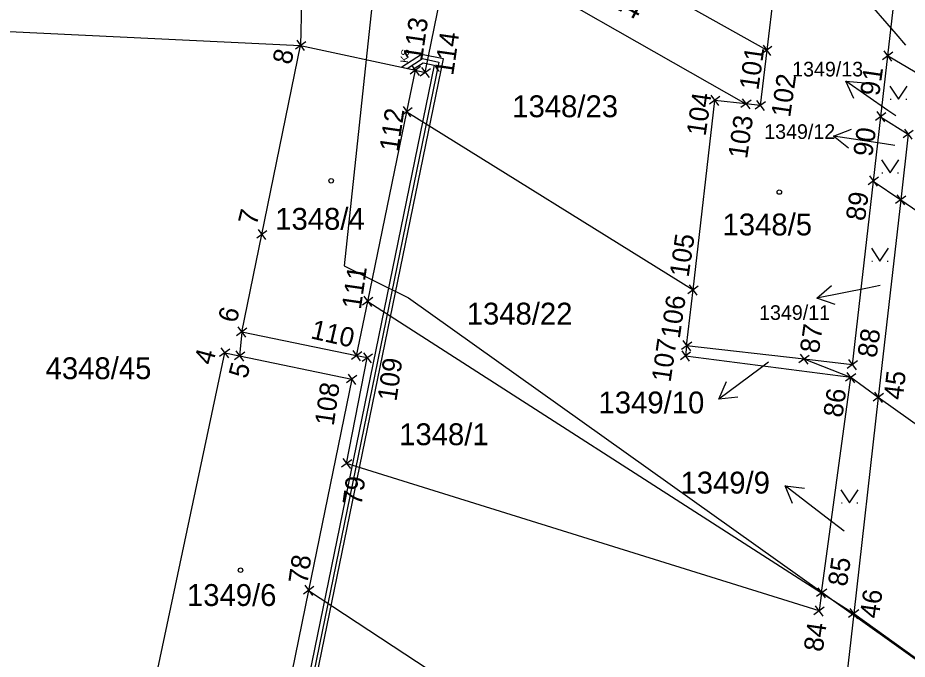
# Model space of a CAD drawing. Extents: x -735036 to -734743, y -1144813 to -1144181.
# Drawn here: x -734915.4 to -734846.3, y -1144656.1 to -1144606.2 of the extents above; entities that cross this region are included whole.
import ezdxf

# ---------------------------------------------------------------- set-up
doc = ezdxf.new("R2010")
doc.units = 0
for name, color, linetype in [('A3_SIT_OBJEKTY_N01', 7, 'Continuous'), ('BPEJ', 7, 'Continuous'), ('CKEL_VEDENI_NN_PODZ_N', 7, 'Continuous'), ('CKTEXTY_MALE', 7, 'Continuous'), ('Groma (60)', 7, 'Continuous'), ('Katastr_HRANICE DRÁHY', 7, 'Continuous'), ('Katastr_Hranice parcel', 7, 'Continuous'), ('Katastr_Parcelní čísla', 7, 'Continuous'), ('Katastr_Značky kultur', 7, 'Continuous')]:
    doc.layers.add(name, color=color, linetype=linetype)

# ---------------------------------------------------------------- blocks, each defined once
blk = doc.blocks.new('POINT_DISPLAY')
for p, q in [((-0.35, -0.35), (0.35, 0.35)), ((-0.35, 0.35), (0.35, -0.35))]:
    blk.add_line(p, q)

msp = doc.modelspace()

# ---------------------------------------------------------------- linework, layer by layer
at = {"layer": 'A3_SIT_OBJEKTY_N01'}
msp.add_lwpolyline([(-734888.186, -1144663.779), (-734888.205, -1144663.881), (-734887.123, -1144664.08), (-734886.924, -1144662.998), (-734888.006, -1144662.799), (-734888.078, -1144663.189), (-734893.105, -1144662.162), (-734882.299, -1144609.423), (-734883.984, -1144609.076), (-734885.528, -1144610.071), (-734884.699, -1144610.25), (-734883.865, -1144609.713), (-734883.007, -1144609.89), (-734893.813, -1144662.63)], close=True, dxfattribs=at)
at = {"layer": 'BPEJ'}
msp.add_lwpolyline([(-734886.95, -1144596.85), (-734888.29, -1144609.47), (-734890, -1144625.5), (-734887.82, -1144626.59), (-734885, -1144628), (-734852.91, -1144650.88), (-734852.15, -1144651.42), (-734850.43, -1144652.65), (-734834.73, -1144663.85), (-734834.99, -1144666), (-734826.29, -1144672.48), (-734825.67, -1144670.31), (-734820.68, -1144673.87), (-734820.5, -1144674), (-734820.82, -1144674.78), (-734818.52, -1144675.9), (-734816.23, -1144677.02), (-734810.97, -1144679.57), (-734807.09, -1144681.45), (-734806.63, -1144681.68), (-734805.5, -1144680.5), (-734802.5, -1144683.25), (-734799.5, -1144686)], dxfattribs=at)
at = {"layer": 'CKEL_VEDENI_NN_PODZ_N'}
msp.add_lwpolyline([(-734885.114, -1144610.161), (-734883.925, -1144609.395), (-734882.653, -1144609.657), (-734893.459, -1144662.396), (-734887.667, -1144663.579)], dxfattribs=at)
at = {"layer": 'Katastr_HRANICE DRÁHY'}
msp.add_line((-734906.57, -1144666.66), (-734899.28, -1144632.27), dxfattribs=at)
for points in [[(-734893.32, -1144605), (-734893.39, -1144608.37)], [(-734896.4, -1144623.07), (-734893.39, -1144608.37)], [(-734846.19, -1144615.27), (-734846.77, -1144620.37)], [(-734846.77, -1144620.37), (-734848.51, -1144635.73)], [(-734897.96, -1144630.65), (-734896.4, -1144623.07)], [(-734897.96, -1144630.65), (-734898.12, -1144632.51)], [(-734899.28, -1144632.27), (-734898.12, -1144632.51)], [(-734848.51, -1144635.73), (-734850.42, -1144652.54)], [(-734850.42, -1144652.54), (-734853.15, -1144676.61)]]:
    msp.add_lwpolyline(points, dxfattribs=at)
at = {"layer": 'Katastr_Hranice parcel'}
for points in [[(-734857.17, -1144608.74), (-734880.66, -1144595.58)], [(-734883.7, -1144610.47), (-734881.55, -1144599.93)], [(-734881.55, -1144599.93), (-734858.79, -1144612.91)], [(-734846.8, -1144600.6), (-734847.79, -1144609.19)], [(-734856.63, -1144604.15), (-734857.17, -1144608.74)], [(-734916.03, -1144607.28), (-734893.39, -1144608.37)], [(-734893.39, -1144608.37), (-734884.47, -1144610.3)], [(-734857.17, -1144608.74), (-734857.68, -1144613.04)], [(-734847.79, -1144609.19), (-734848.33, -1144613.91)], [(-734845.64, -1144610.44), (-734847.79, -1144609.19)], [(-734885.13, -1144613.52), (-734884.47, -1144610.3)], [(-734884.47, -1144610.3), (-734883.7, -1144610.47)], [(-734862.9, -1144627.38), (-734861.22, -1144612.64)], [(-734858.79, -1144612.91), (-734861.22, -1144612.64)], [(-734857.68, -1144613.04), (-734858.79, -1144612.91)], [(-734888.17, -1144628.27), (-734885.13, -1144613.52)], [(-734885.13, -1144613.52), (-734862.9, -1144627.38)], [(-734848.33, -1144613.91), (-734848.9, -1144618.91)], [(-734848.33, -1144613.91), (-734846.19, -1144615.27)], [(-734848.9, -1144618.91), (-734850.53, -1144633.19)], [(-734848.9, -1144618.91), (-734846.77, -1144620.37)], [(-734846.77, -1144620.37), (-734841.89, -1144623.71)], [(-734863.4, -1144631.72), (-734862.9, -1144627.38)], [(-734889.04, -1144632.49), (-734888.17, -1144628.27)], [(-734888.17, -1144628.27), (-734852.92, -1144650.93)], [(-734889.04, -1144632.49), (-734897.96, -1144630.65)], [(-734863.4, -1144631.72), (-734863.49, -1144632.52)], [(-734854.28, -1144632.76), (-734863.4, -1144631.72)], [(-734898.12, -1144632.51), (-734889.41, -1144634.32)], [(-734889.81, -1144640.87), (-734888.21, -1144632.66)], [(-734888.21, -1144632.66), (-734889.04, -1144632.49)], [(-734850.65, -1144634.19), (-734863.49, -1144632.52)], [(-734850.53, -1144633.19), (-734854.28, -1144632.76)], [(-734850.65, -1144634.19), (-734854.28, -1144632.76)], [(-734889.41, -1144634.32), (-734892.76, -1144650.74)], [(-734852.92, -1144650.93), (-734850.65, -1144634.19)], [(-734848.51, -1144635.73), (-734850.65, -1144634.19)], [(-734843.69, -1144639.2), (-734848.51, -1144635.73)], [(-734853.11, -1144652.34), (-734889.81, -1144640.87)], [(-734892.76, -1144650.74), (-734896.42, -1144668.65)], [(-734892.76, -1144650.74), (-734868.44, -1144666.76)], [(-734852.92, -1144650.93), (-734853.11, -1144652.34)], [(-734852.92, -1144650.93), (-734850.42, -1144652.54)], [(-734850.42, -1144652.54), (-734845.63, -1144655.97)]]:
    msp.add_lwpolyline(points, dxfattribs=at)
at = {"layer": 'Katastr_Parcelní čísla'}
for p, q in [((-734846.36, -1144608.35), (-734847.12, -1144607.47)), ((-734850.404, -1144612.501), (-734851.041, -1144611.143)), ((-734847.15, -1144613.85), (-734847.76, -1144613.43)), ((-734850.822, -1144616.36), (-734851.996, -1144615.425)), ((-734847.22, -1144616.14), (-734848.04, -1144616.02)), ((-734848.37, -1144627.04), (-734849.36, -1144627.24)), ((-734851.859, -1144628.507), (-734853.282, -1144628.028)), ((-734857.03, -1144632.99), (-734857.7, -1144633.49)), ((-734859.416, -1144635.706), (-734860.906, -1144635.882)), ((-734855.173, -1144643.989), (-734855.741, -1144642.599)), ((-734851.17, -1144646.14), (-734852.58, -1144645.05))]:
    msp.add_line(p, q, dxfattribs=at)
for points in [[(-734847.12, -1144607.47), (-734849.734, -1144604.442), (-734848.317, -1144604.936)], [(-734847.76, -1144613.43), (-734851.041, -1144611.143), (-734849.546, -1144611.271)], [(-734848.04, -1144616.02), (-734851.996, -1144615.425), (-734850.598, -1144614.877)], [(-734849.36, -1144627.24), (-734853.282, -1144628.028), (-734852.155, -1144627.037)], [(-734857.7, -1144633.49), (-734860.906, -1144635.882), (-734860.313, -1144634.503)], [(-734852.58, -1144645.05), (-734855.741, -1144642.599), (-734854.255, -1144642.803)]]:
    msp.add_lwpolyline(points, dxfattribs=at)
at = {"layer": 'Katastr_Značky kultur'}
for p, q in [((-734847.61, -1144611.545), (-734846.94, -1144612.55)), ((-734846.94, -1144612.55), (-734846.27, -1144611.545)), ((-734847.577, -1144612.55), (-734847.51, -1144612.55)), ((-734846.371, -1144612.55), (-734846.304, -1144612.55)), ((-734848.26, -1144617.265), (-734847.59, -1144618.27)), ((-734847.59, -1144618.27), (-734846.92, -1144617.265)), ((-734848.226, -1144618.27), (-734848.16, -1144618.27)), ((-734847.02, -1144618.27), (-734846.954, -1144618.27)), ((-734849.05, -1144624.125), (-734848.38, -1144625.13)), ((-734848.38, -1144625.13), (-734847.71, -1144624.125)), ((-734849.017, -1144625.13), (-734848.95, -1144625.13)), ((-734847.811, -1144625.13), (-734847.743, -1144625.13)), ((-734851.41, -1144642.925), (-734850.74, -1144643.93)), ((-734850.74, -1144643.93), (-734850.07, -1144642.925)), ((-734851.377, -1144643.93), (-734851.31, -1144643.93)), ((-734850.171, -1144643.93), (-734850.103, -1144643.93))]:
    msp.add_line(p, q, dxfattribs=at)
for centre in [(-734891.01, -1144618.89), (-734856.2, -1144619.77), (-734898.05, -1144649.17)]:
    msp.add_circle(centre, 0.175, dxfattribs=at)

# ---------------------------------------------------------------- block references
at = {"layer": 'Groma (60)', "rotation": -98.65482414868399}
for p in [(-734893.39, -1144608.37), (-734857.17, -1144608.74), (-734847.79, -1144609.19), (-734884.47, -1144610.3), (-734883.7, -1144610.47), (-734861.22, -1144612.64), (-734858.79, -1144612.91), (-734857.68, -1144613.04), (-734885.13, -1144613.52), (-734848.33, -1144613.91), (-734846.19, -1144615.27), (-734848.9, -1144618.91), (-734846.77, -1144620.37), (-734896.4, -1144623.07), (-734862.9, -1144627.38), (-734888.17, -1144628.27), (-734897.96, -1144630.65), (-734863.4, -1144631.72), (-734899.28, -1144632.27), (-734898.12, -1144632.51), (-734889.04, -1144632.49), (-734888.21, -1144632.66), (-734863.49, -1144632.52), (-734854.28, -1144632.76), (-734850.53, -1144633.19), (-734889.41, -1144634.32), (-734850.65, -1144634.19), (-734848.51, -1144635.73), (-734889.81, -1144640.87), (-734892.76, -1144650.74), (-734852.92, -1144650.93), (-734853.11, -1144652.34), (-734850.42, -1144652.54)]:
    msp.add_blockref('POINT_DISPLAY', p, dxfattribs=at)

# ---------------------------------------------------------------- texts
at = {"layer": 'CKTEXTY_MALE'}
msp.add_text('KS', height=0.6, rotation=83.326, dxfattribs=at).set_placement((-734885.059, -1144609.751))
at = {"layer": 'Groma (60)'}
for s, rotation, p in [('113', 81.78352, (-734883.951, -1144609.621)), ('114', 81.78352, (-734881.535, -1144610.751)), ('8', 77.45483, (-734894.132, -1144609.923)), ('101', 81.78352, (-734857.831, -1144611.901)), ('91', 81.78352, (-734848.451, -1144612.351)), ('102', 81.78352, (-734855.361, -1144614.009)), ('104', 81.78352, (-734861.933, -1144615.466)), ('112', 81.78352, (-734885.791, -1144616.681)), ('103', 81.78352, (-734858.705, -1144617.229)), ('90', 81.78352, (-734848.991, -1144617.071)), ('89', 81.78352, (-734849.561, -1144622.071)), ('7', 76.17681, (-734896.811, -1144622.426)), ('105', 81.78352, (-734863.25, -1144626.439)), ('111', 81.78352, (-734888.709, -1144628.943)), ('106', 81.78352, (-734863.937, -1144631.213)), ('6', 76.17681, (-734898.371, -1144630.006)), ('110', 347.16151, (-734892.672, -1144631.13)), ('87', 81.78352, (-734853.135, -1144632.356)), ('88', 81.78352, (-734848.659, -1144632.706)), ('107', 81.78352, (-734864.648, -1144634.6)), ('4', 74.80842, (-734900.235, -1144633.285)), ('5', 75.37884, (-734897.557, -1144634.339)), ('109', 81.78352, (-734885.943, -1144636.089)), ('45', 83.1202, (-734846.624, -1144635.973)), ('108', 81.78352, (-734890.818, -1144637.996)), ('86', 81.78352, (-734851.311, -1144637.351)), ('79', 81.78352, (-734888.659, -1144644.188)), ('78', 81.78352, (-734892.859, -1144650.29)), ('85', 81.78352, (-734850.956, -1144650.481)), ('46', 81.90204, (-734848.482, -1144652.977)), ('84', 81.78352, (-734852.836, -1144655.564))]:
    msp.add_text(s, height=1.5, rotation=rotation, dxfattribs=at).set_placement(p)
at = {"layer": 'Katastr_Parcelní čísla'}
msp.add_text('1348/24', height=1.7, rotation=331.31088, dxfattribs=at).set_placement((-734874.487, -1144602.47))
for s, height, p in [('1349/13', 1.14, (-734855.201, -1144610.78)), ('1348/23', 1.7, (-734876.944, -1144613.95)), ('1349/12', 1.14, (-734857.371, -1144615.64)), ('1348/4', 1.7, (-734895.356, -1144622.7)), ('1348/5', 1.7, (-734860.61, -1144623.14)), ('1348/22', 1.7, (-734880.484, -1144630.07)), ('1349/11', 1.14, (-734857.77, -1144629.71)), ('4348/45', 1.7, (-734913.195, -1144634.317)), ('1349/10', 1.7, (-734870.243, -1144636.98)), ('1348/1', 1.7, (-734885.729, -1144639.45)), ('1349/9', 1.7, (-734863.879, -1144643.21)), ('1349/6', 1.7, (-734902.214, -1144651.95))]:
    msp.add_text(s, height=height, dxfattribs=at).set_placement(p)

doc.saveas('drawing.dxf')
